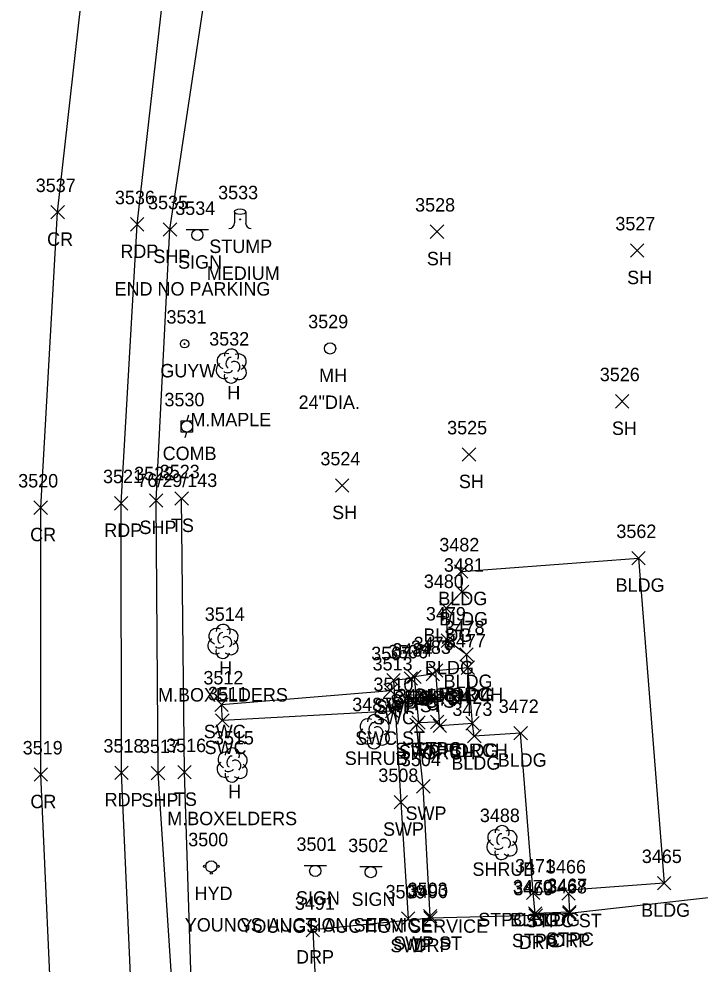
# Model space of a CAD drawing. Extents: x 1769141 to 1770911, y 735471 to 741449.
# Drawn here: x 1770463.6 to 1770565, y 737822.4 to 737963 of the extents above; entities that cross this region are included whole.
import ezdxf

# ---------------------------------------------------------------- set-up
doc = ezdxf.new("R2010")
doc.units = 0
for name, color, linetype in [('L_A', 7, 'Continuous'), ('L_C', 7, 'Continuous'), ('L_I', 7, 'Continuous'), ('L_TIC', 7, 'Continuous'), ('LBC', 7, 'Continuous'), ('LBF', 7, 'Continuous'), ('LELB', 7, 'Continuous'), ('LSH', 7, 'Continuous'), ('LTD', 7, 'Continuous'), ('LTS', 7, 'Continuous'), ('P_A', 7, 'Continuous'), ('P_I', 7, 'Continuous'), ('P_TIC', 7, 'Continuous'), ('PET', 7, 'Continuous'), ('PRC', 7, 'Continuous'), ('PSP', 7, 'Continuous'), ('R_A', 7, 'Continuous'), ('R_I', 7, 'Continuous'), ('R_TIC', 7, 'Continuous'), ('RDP', 7, 'Continuous'), ('RSW', 7, 'Continuous'), ('S_A', 7, 'Continuous'), ('S_C', 7, 'Continuous'), ('S_I', 7, 'Continuous'), ('SSGN', 7, 'Continuous'), ('U_A', 7, 'Continuous'), ('U_C', 7, 'Continuous'), ('U_I', 7, 'Continuous'), ('UP', 7, 'Continuous'), ('UPGW', 7, 'Continuous'), ('UUMH', 7, 'Continuous'), ('UWFH', 7, 'Continuous')]:
    doc.layers.add(name, color=color, linetype=linetype)

msp = doc.modelspace()

# ---------------------------------------------------------------- linework, layer by layer
at = {"layer": 'L_TIC'}
for points in [[(1770524.81, 737930.33), (1770526.81, 737932.33)], [(1770526.81, 737930.33), (1770524.81, 737932.33)], [(1770554.62, 737927.53), (1770556.62, 737929.53)], [(1770556.62, 737927.53), (1770554.62, 737929.53)], [(1770552.36, 737905.1), (1770554.36, 737907.1)], [(1770554.36, 737905.1), (1770552.36, 737907.1)], [(1770529.58, 737897.19), (1770531.58, 737899.19)], [(1770531.58, 737897.19), (1770529.58, 737899.19)], [(1770510.71, 737892.58), (1770512.71, 737894.58)], [(1770512.71, 737892.58), (1770510.71, 737894.58)], [(1770486.8, 737890.66), (1770488.8, 737892.66)], [(1770488.8, 737890.66), (1770486.8, 737892.66)], [(1770554.81, 737881.77), (1770556.81, 737883.77)], [(1770556.81, 737881.77), (1770554.81, 737883.77)], [(1770528.41, 737879.78), (1770530.41, 737881.78)], [(1770530.41, 737879.78), (1770528.41, 737881.78)], [(1770528.53, 737876.76), (1770530.53, 737878.76)], [(1770530.53, 737876.76), (1770528.53, 737878.76)], [(1770526.19, 737874.33), (1770528.19, 737876.33)], [(1770528.19, 737874.33), (1770526.19, 737876.33)], [(1770526.43, 737869.5), (1770528.43, 737871.5)], [(1770528.43, 737869.5), (1770526.43, 737871.5)], [(1770529.2, 737867.46), (1770531.2, 737869.46)], [(1770531.2, 737867.46), (1770529.2, 737869.46)], [(1770529.39, 737865.49), (1770531.39, 737867.49)], [(1770531.39, 737865.49), (1770529.39, 737867.49)], [(1770529.39, 737865.49), (1770531.39, 737867.49)], [(1770531.39, 737865.49), (1770529.39, 737867.49)], [(1770521.43, 737864.13), (1770523.43, 737866.13)], [(1770523.43, 737864.13), (1770521.43, 737866.13)], [(1770524.19, 737864.53), (1770526.19, 737866.53)], [(1770526.19, 737864.53), (1770524.19, 737866.53)], [(1770524.66, 737865.08), (1770526.66, 737867.08)], [(1770526.66, 737865.08), (1770524.66, 737867.08)], [(1770522.07, 737857.32), (1770524.07, 737859.32)], [(1770524.07, 737857.32), (1770522.07, 737859.32)], [(1770524.82, 737857.41), (1770526.82, 737859.41)], [(1770526.82, 737857.41), (1770524.82, 737859.41)], [(1770525.24, 737856.84), (1770527.24, 737858.84)], [(1770527.24, 737856.84), (1770525.24, 737858.84)], [(1770530.08, 737857.2), (1770532.08, 737859.2)], [(1770532.08, 737857.2), (1770530.08, 737859.2)], [(1770530.08, 737857.2), (1770532.08, 737859.2)], [(1770532.08, 737857.2), (1770530.08, 737859.2)], [(1770537.26, 737855.75), (1770539.26, 737857.75)], [(1770539.26, 737855.75), (1770537.26, 737857.75)], [(1770530.36, 737855.31), (1770532.36, 737857.31)], [(1770532.36, 737855.31), (1770530.36, 737857.31)], [(1770487.24, 737849.93), (1770489.24, 737851.93)], [(1770489.24, 737849.93), (1770487.24, 737851.93)], [(1770558.61, 737833.43), (1770560.61, 737835.43)], [(1770560.61, 737833.43), (1770558.61, 737835.43)], [(1770539.12, 737832.02), (1770541.12, 737834.02)], [(1770541.12, 737832.02), (1770539.12, 737834.02)], [(1770539.12, 737832.02), (1770541.12, 737834.02)], [(1770541.12, 737832.02), (1770539.12, 737834.02)], [(1770544.4, 737831.88), (1770546.4, 737833.88)], [(1770546.4, 737831.88), (1770544.4, 737833.88)], [(1770539.44, 737828.91), (1770541.44, 737830.91)], [(1770541.44, 737828.91), (1770539.44, 737830.91)], [(1770544.53, 737829.11), (1770546.53, 737831.11)], [(1770546.53, 737829.11), (1770544.53, 737831.11)]]:
    msp.add_lwpolyline(points, dxfattribs=at)
at = {"layer": 'LBC'}
for points in [[(1770559.61, 737834.43), (1770540.12, 737833.02), (1770538.26, 737856.75), (1770531.36, 737856.31), (1770531.08, 737858.2), (1770530.39, 737866.49), (1770530.2, 737868.46), (1770527.43, 737870.5), (1770527.19, 737875.33), (1770529.53, 737877.76), (1770529.41, 737880.78), (1770555.81, 737882.77)], [(1770555.81, 737882.77), (1770559.61, 737834.43)]]:
    msp.add_lwpolyline(points, dxfattribs=at)
at = {"layer": 'LBF'}
for points in [[(1770531.08, 737858.2), (1770526.24, 737857.84), (1770525.66, 737866.08), (1770530.39, 737866.49)], [(1770525.19, 737865.53), (1770522.43, 737865.13), (1770523.07, 737858.32), (1770525.82, 737858.41)], [(1770545.4, 737832.88), (1770545.53, 737830.11), (1770540.44, 737829.91), (1770540.12, 737833.02)]]:
    msp.add_lwpolyline(points, dxfattribs=at)
at = {"layer": 'LELB'}
msp.add_lwpolyline([(1770492.86, 737807.44), (1770489.41, 737813.76), (1770488.24, 737850.93), (1770487.8, 737891.66)], dxfattribs=at)
at = {"layer": 'LSH'}
for p, q in [((1770516.45, 737857.02), (1770516.45, 737857.02)), ((1770516.45, 737857.02), (1770516.45, 737857.02)), ((1770535.45, 737840.52), (1770535.45, 737840.52)), ((1770535.45, 737840.52), (1770535.45, 737840.52))]:
    msp.add_line(p, q, dxfattribs=at)
for centre in [(1770516.5, 737858.46), (1770535.5, 737841.95)]:
    msp.add_arc(centre, 1.05, 335.5272, 180.9563, dxfattribs=at)
for centre, major_axis, ratio, start_param, end_param in [((1770515.66, 737857.69), (1.21, -0.51), 0.895232, 1.570796, 4.712389), ((1770517.49, 737857.61), (-1.14, -0.48), 0.949671, 1.570796, 4.712389), ((1770515.37, 737856.32), (0.58, -1.04), 0.959034, 3.141593, 6.283185), ((1770516.24, 737857.48), (-0.208, -0.792), 0.645439, 3.141593, 6.283185), ((1770516.95, 737856.86), (-0.5, 0.667), 0.989748, 3.141593, 6.283185), ((1770515.99, 737856.27), (-0.625, -0.083), 0.423636, 0, 3.141593), ((1770517.45, 737856.19), (-1.09, 0.79), 0.841452, 1.570796, 4.712389), ((1770516.45, 737855.52), (0.26, 1.06), 0.942809, 1.570796, 4.712389), ((1770534.66, 737841.19), (1.21, -0.51), 0.895232, 1.570796, 4.712389), ((1770536.5, 737841.1), (-1.14, -0.48), 0.949671, 1.570796, 4.712389), ((1770534.37, 737839.81), (0.58, -1.04), 0.959034, 3.141593, 6.283185), ((1770535.25, 737840.98), (-0.208, -0.792), 0.645439, 3.141593, 6.283185), ((1770535.95, 737840.35), (-0.5, 0.667), 0.989748, 3.141593, 6.283185), ((1770536.45, 737839.69), (-1.09, 0.79), 0.841452, 1.570796, 4.712389), ((1770535.45, 737839.02), (0.26, 1.06), 0.942809, 1.570796, 4.712389), ((1770535, 737839.77), (-0.625, -0.083), 0.423636, 0, 3.141593)]:
    msp.add_ellipse(centre, major_axis=major_axis, ratio=ratio, start_param=start_param, end_param=end_param, dxfattribs=at)
at = {"layer": 'LTD'}
for p, q in [((1770495.16, 737911.39), (1770495.16, 737911.39)), ((1770495.16, 737911.39), (1770495.16, 737911.39)), ((1770493.93, 737870.45), (1770493.93, 737870.45)), ((1770493.93, 737870.45), (1770493.93, 737870.45)), ((1770495.3, 737852.06), (1770495.3, 737852.06)), ((1770495.3, 737852.06), (1770495.3, 737852.06))]:
    msp.add_line(p, q, dxfattribs=at)
for centre in [(1770495.21, 737912.82), (1770493.98, 737871.88), (1770495.35, 737853.5)]:
    msp.add_arc(centre, 1.05, 335.5272, 180.9563, dxfattribs=at)
for centre, major_axis, ratio, start_param, end_param in [((1770494.37, 737912.06), (1.21, -0.51), 0.895232, 1.570796, 4.712389), ((1770494.95, 737911.85), (-0.208, -0.792), 0.645439, 3.141593, 6.283185), ((1770495.66, 737911.22), (-0.5, 0.667), 0.989748, 3.141593, 6.283185), ((1770496.2, 737911.97), (-1.14, -0.48), 0.949671, 1.570796, 4.712389), ((1770494.08, 737910.68), (0.58, -1.04), 0.959034, 3.141593, 6.283185), ((1770496.16, 737910.56), (-1.09, 0.79), 0.841452, 1.570796, 4.712389), ((1770495.16, 737909.89), (0.26, 1.06), 0.942809, 1.570796, 4.712389), ((1770494.71, 737910.64), (-0.625, -0.083), 0.423636, 0, 3.141593), ((1770493.14, 737871.12), (1.21, -0.51), 0.895232, 1.570796, 4.712389), ((1770493.72, 737870.91), (-0.208, -0.792), 0.645439, 3.141593, 6.283185), ((1770494.97, 737871.03), (-1.14, -0.48), 0.949671, 1.570796, 4.712389), ((1770492.85, 737869.74), (0.58, -1.04), 0.959034, 3.141593, 6.283185), ((1770494.43, 737870.28), (-0.5, 0.667), 0.989748, 3.141593, 6.283185), ((1770494.93, 737869.62), (-1.09, 0.79), 0.841452, 1.570796, 4.712389), ((1770493.93, 737868.95), (0.26, 1.06), 0.942809, 1.570796, 4.712389), ((1770493.47, 737869.7), (-0.625, -0.083), 0.423636, 0, 3.141593), ((1770494.51, 737852.73), (1.21, -0.51), 0.895232, 1.570796, 4.712389), ((1770495.09, 737852.52), (-0.208, -0.792), 0.645439, 3.141593, 6.283185), ((1770496.34, 737852.65), (-1.14, -0.48), 0.949671, 1.570796, 4.712389), ((1770494.22, 737851.36), (0.58, -1.04), 0.959034, 3.141593, 6.283185), ((1770495.8, 737851.9), (-0.5, 0.667), 0.989748, 3.141593, 6.283185), ((1770496.3, 737851.23), (-1.09, 0.79), 0.841452, 1.570796, 4.712389), ((1770495.3, 737850.56), (0.26, 1.06), 0.942809, 1.570796, 4.712389), ((1770494.84, 737851.31), (-0.625, -0.083), 0.423636, 0, 3.141593)]:
    msp.add_ellipse(centre, major_axis=major_axis, ratio=ratio, start_param=start_param, end_param=end_param, dxfattribs=at)
at = {"layer": 'LTS'}
for p, q in [((1770495.66, 737934.3), (1770495.66, 737932.63)), ((1770497.33, 737934.13), (1770497.33, 737934.3)), ((1770497.33, 737934.3), (1770497.33, 737932.63)), ((1770496.5, 737933.16), (1770496.5, 737933.16)), ((1770496.5, 737933.16), (1770496.5, 737933.16)), ((1770496.5, 737933.13), (1770496.5, 737933.13))]:
    msp.add_line(p, q, dxfattribs=at)
msp.add_circle((1770496.5, 737933.16), 0.0833, dxfattribs=at)
for centre, start, end in [((1770494.83, 737932.63), 270, 360), ((1770498.16, 737932.63), 180, 270)]:
    msp.add_arc(centre, 0.833, start, end, dxfattribs=at)
msp.add_ellipse((1770496.5, 737934.3), major_axis=(-0.833, 0), ratio=0.5, dxfattribs=at)
at = {"layer": 'P_TIC'}
for points in [[(1770468.34, 737933.23), (1770470.34, 737935.23)], [(1770470.34, 737933.23), (1770468.34, 737935.23)], [(1770480.19, 737931.42), (1770482.19, 737933.42)], [(1770482.19, 737931.42), (1770480.19, 737933.42)], [(1770485.06, 737930.67), (1770487.06, 737932.67)], [(1770487.06, 737930.67), (1770485.06, 737932.67)], [(1770465.82, 737889.29), (1770467.82, 737891.29)], [(1770467.82, 737889.29), (1770465.82, 737891.29)], [(1770477.8, 737889.93), (1770479.8, 737891.93)], [(1770479.8, 737889.93), (1770477.8, 737891.93)], [(1770482.99, 737890.36), (1770484.99, 737892.36)], [(1770484.99, 737890.36), (1770482.99, 737892.36)], [(1770477.86, 737849.86), (1770479.86, 737851.86)], [(1770479.86, 737849.86), (1770477.86, 737851.86)], [(1770483.28, 737849.79), (1770485.28, 737851.79)], [(1770485.28, 737849.79), (1770483.28, 737851.79)], [(1770465.84, 737849.58), (1770467.84, 737851.58)], [(1770467.84, 737849.58), (1770465.84, 737851.58)]]:
    msp.add_lwpolyline(points, dxfattribs=at)
at = {"layer": 'PET'}
msp.add_lwpolyline([(1770480.71, 737808.5), (1770478.86, 737850.86), (1770478.8, 737890.93), (1770481.19, 737932.42), (1770486.18, 737976.53), (1770491.62, 738013.47), (1770502.41, 738078.7), (1770511.1, 738132.78), (1770519.35, 738183.15), (1770528.05, 738233.56)], dxfattribs=at)
at = {"layer": 'PRC'}
msp.add_lwpolyline([(1770468.76, 737807.58), (1770466.84, 737850.58), (1770466.82, 737890.29), (1770469.34, 737934.23), (1770474.31, 737978.71), (1770479.69, 738015.04), (1770490.28, 738081.51), (1770499.05, 738134.54), (1770507.77, 738186.68), (1770516.39, 738236.25)], dxfattribs=at)
at = {"layer": 'PSP'}
msp.add_lwpolyline([(1770486.55, 737816.81), (1770484.28, 737850.79), (1770483.99, 737891.36), (1770486.06, 737931.67), (1770492.57, 737975.17), (1770497.3, 738012.43), (1770501.89, 738042.39), (1770501.76, 738044.7), (1770499.5, 738044.97), (1770500.56, 738049.22), (1770502.3, 738050.11), (1770506.67, 738077.79), (1770511.72, 738105.49), (1770515.85, 738132.28), (1770518.33, 738152.88), (1770523.83, 738182.57), (1770531.42, 738212.51), (1770539.31, 738265.32)], dxfattribs=at)
at = {"layer": 'R_TIC'}
for points in [[(1770520.93, 737863.87), (1770522.93, 737865.87)], [(1770522.93, 737863.87), (1770520.93, 737865.87)], [(1770518.35, 737863.6), (1770520.35, 737865.6)], [(1770520.35, 737863.6), (1770518.35, 737865.6)], [(1770517.92, 737862.07), (1770519.92, 737864.07)], [(1770519.92, 737862.07), (1770517.92, 737864.07)], [(1770492.73, 737859.99), (1770494.73, 737861.99)], [(1770494.73, 737859.99), (1770492.73, 737861.99)], [(1770518.13, 737859.01), (1770520.13, 737861.01)], [(1770520.13, 737859.01), (1770518.13, 737861.01)], [(1770492.86, 737857.63), (1770494.86, 737859.63)], [(1770494.86, 737857.63), (1770492.86, 737859.63)], [(1770521.78, 737857), (1770523.78, 737859)], [(1770523.78, 737857), (1770521.78, 737859)], [(1770522.77, 737847.84), (1770524.77, 737849.84)], [(1770524.77, 737847.84), (1770522.77, 737849.84)], [(1770519.42, 737845.48), (1770521.42, 737847.48)], [(1770521.42, 737845.48), (1770519.42, 737847.48)], [(1770539.49, 737828.63), (1770541.49, 737830.63)], [(1770541.49, 737828.63), (1770539.49, 737830.63)], [(1770544.48, 737828.91), (1770546.48, 737830.91)], [(1770546.48, 737828.91), (1770544.48, 737830.91)], [(1770520.51, 737828.16), (1770522.51, 737830.16)], [(1770522.51, 737828.16), (1770520.51, 737830.16)], [(1770523.78, 737828.51), (1770525.78, 737830.51)], [(1770525.78, 737828.51), (1770523.78, 737830.51)], [(1770523.84, 737828.21), (1770525.84, 737830.21)], [(1770525.84, 737828.21), (1770523.84, 737830.21)], [(1770506.34, 737826.47), (1770508.34, 737828.47)], [(1770508.34, 737826.47), (1770506.34, 737828.47)]]:
    msp.add_lwpolyline(points, dxfattribs=at)
at = {"layer": 'RDP'}
msp.add_lwpolyline([(1770490.29, 737787.37), (1770507.99, 737789.23), (1770543.91, 737792.74), (1770589.63, 737792.76), (1770587.83, 737818.09), (1770572.93, 737817.31), (1770571.5, 737832.84), (1770545.48, 737829.91), (1770540.49, 737829.63), (1770524.84, 737829.21), (1770507.34, 737827.47), (1770508.38, 737805.41), (1770496.94, 737803.45), (1770492.73, 737804.13), (1770488.37, 737807.82)], dxfattribs=at)
at = {"layer": 'RSW'}
for points in [[(1770521.93, 737864.87), (1770519.35, 737864.6), (1770520.42, 737846.48), (1770521.51, 737829.16)], [(1770519.13, 737860.01), (1770493.86, 737858.63), (1770493.73, 737860.99), (1770518.92, 737863.07)], [(1770524.78, 737829.51), (1770523.77, 737848.84), (1770522.78, 737858)]]:
    msp.add_lwpolyline(points, dxfattribs=at)
at = {"layer": 'SSGN'}
for p, q in [((1770488.48, 737931.68), (1770491.82, 737931.68)), ((1770490.13, 737930.85), (1770490.13, 737930.85)), ((1770506.03, 737837.08), (1770509.36, 737837.08)), ((1770507.68, 737836.25), (1770507.68, 737836.25)), ((1770514.31, 737836.91), (1770517.64, 737836.91)), ((1770515.95, 737836.07), (1770515.95, 737836.07))]:
    msp.add_line(p, q, dxfattribs=at)
for centre in [(1770490.13, 737930.85), (1770507.68, 737836.25), (1770515.95, 737836.07)]:
    msp.add_circle(centre, 0.833, dxfattribs=at)
at = {"layer": 'UP'}
for p, q in [((1770488.83, 737904.03), (1770488.58, 737903.2)), ((1770487.75, 737901.53), (1770487.75, 737903.2)), ((1770487.75, 737903.2), (1770489.42, 737903.2)), ((1770488.58, 737902.36), (1770488.58, 737902.36)), ((1770489.42, 737903.2), (1770489.42, 737901.53)), ((1770489.42, 737901.53), (1770487.75, 737901.53)), ((1770488.33, 737900.7), (1770488.58, 737901.53))]:
    msp.add_line(p, q, dxfattribs=at)
msp.add_circle((1770488.58, 737902.36), 0.833, dxfattribs=at)
at = {"layer": 'UPGW'}
for radius in [0.625, 0.0833]:
    msp.add_circle((1770488.23, 737914.66), radius, dxfattribs=at)
at = {"layer": 'UUMH'}
for p, q in [((1770509.9, 737913.97), (1770509.9, 737913.97)), ((1770510.74, 737913.97), (1770510.74, 737913.97))]:
    msp.add_line(p, q, dxfattribs=at)
msp.add_circle((1770509.9, 737913.97), 0.833, dxfattribs=at)
at = {"layer": 'UWFH'}
msp.add_line((1770492.21, 737836.92), (1770492.21, 737836.92), dxfattribs=at)
for centre, radius in [((1770492.21, 737836.92), 0.833), ((1770491.21, 737836.92), 0.167), ((1770493.21, 737836.92), 0.167), ((1770492.21, 737835.92), 0.167)]:
    msp.add_circle(centre, radius, dxfattribs=at)

# ---------------------------------------------------------------- texts
at = {"layer": 'L_A'}
for s, p in [('STUMP', (1770491.92, 737928.16)), ('SH', (1770524.3, 737926.33)), ('SH', (1770554.11, 737923.53)), ('H', (1770494.6, 737906.39)), ('SH', (1770551.85, 737901.1)), ('SH', (1770529.07, 737893.19)), ('SH', (1770510.2, 737888.58)), ('TS', (1770486.21, 737886.66)), ('BLDG', (1770552.4, 737877.77)), ('BLDG', (1770526.01, 737875.78)), ('BLDG', (1770526.12, 737872.76)), ('BLDG', (1770523.78, 737870.33)), ('H', (1770493.37, 737865.45)), ('BLDG', (1770524.02, 737865.5)), ('BLDG', (1770526.79, 737863.46)), ('PORCH', (1770521.28, 737861.08)), ('PORCH', (1770526.01, 737861.49)), ('BLDG', (1770526.98, 737861.49)), ('STPC ST', (1770518.83, 737860.53)), ('STPC', (1770518.94, 737860.13)), ('STPC', (1770519.59, 737853.32)), ('PORCH', (1770521.86, 737852.84)), ('STPC', (1770522.33, 737853.41)), ('PORCH', (1770526.7, 737853.2)), ('BLDG', (1770527.67, 737853.2)), ('SHRUB', (1770512.08, 737852.02)), ('BLDG', (1770527.95, 737851.31)), ('BLDG', (1770534.85, 737851.75)), ('H', (1770494.73, 737847.06)), ('TS', (1770486.65, 737845.93)), ('SHRUB', (1770531.08, 737835.52)), ('BLDG', (1770556.2, 737829.43)), ('STPC BLDG', (1770531.95, 737828.02)), ('BLDG', (1770536.71, 737828.02)), ('STPC ST', (1770539.04, 737827.88)), ('STPC', (1770536.96, 737824.91)), ('STPC', (1770542.04, 737825.11))]:
    msp.add_text(s, height=2, dxfattribs=at).set_placement(p)
at = {"layer": 'L_C'}
for s, p in [('MEDIUM', (1770491.55, 737924.16)), ('M.MAPLE', (1770489.1, 737902.39)), ('M.BOXELDERS', (1770484.29, 737861.45)), ('M.BOXELDERS', (1770485.66, 737843.06))]:
    msp.add_text(s, height=2, dxfattribs=at).set_placement(p)
at = {"layer": 'L_I'}
for s, p in [('3533', (1770493.23, 737936.16)), ('3528', (1770522.55, 737934.33)), ('3527', (1770552.36, 737931.53)), ('3532', (1770491.9, 737914.39)), ('3526', (1770550.04, 737909.1)), ('3525', (1770527.32, 737901.19)), ('3524', (1770508.45, 737896.58)), ('3523', (1770484.54, 737894.66)), ('3562', (1770552.51, 737885.77)), ('3482', (1770526.16, 737883.78)), ('3481', (1770526.83, 737880.76)), ('3480', (1770523.85, 737878.33)), ('3514', (1770491.24, 737873.45)), ('3479', (1770524.16, 737873.5)), ('3478', (1770526.94, 737871.46)), ('3477', (1770527.13, 737869.49)), ('3477', (1770527.13, 737869.49)), ('3484', (1770519.17, 737868.13)), ('3483', (1770521.93, 737868.53)), ('3476', (1770522.34, 737869.08)), ('3485', (1770519.81, 737861.32)), ('3486', (1770522.51, 737861.41)), ('3474', (1770527.82, 737861.2)), ('3474', (1770527.82, 737861.2)), ('3487', (1770513.19, 737860.02)), ('3475', (1770522.98, 737860.84)), ('3472', (1770535, 737859.75)), ('3473', (1770528.1, 737859.31)), ('3516', (1770485.49, 737853.93)), ('3515', (1770492.61, 737855.06)), ('3488', (1770532.19, 737843.52)), ('3465', (1770556.3, 737837.43)), ('3471', (1770537.42, 737836.02)), ('3471', (1770537.42, 737836.02)), ('3466', (1770542.03, 737835.88)), ('3470', (1770537.1, 737832.91)), ('3467', (1770542.22, 737833.11))]:
    msp.add_text(s, height=2, dxfattribs=at).set_placement(p)
at = {"layer": 'P_A'}
for s, p in [('CR', (1770467.77, 737929.23)), ('RDP', (1770478.68, 737927.42)), ('SHP', (1770483.59, 737926.67)), ('SHP', (1770481.52, 737886.36)), ('CR', (1770465.25, 737885.29)), ('RDP', (1770476.28, 737885.93)), ('CR', (1770465.28, 737845.58)), ('RDP', (1770476.34, 737845.86)), ('SHP', (1770481.81, 737845.79))]:
    msp.add_text(s, height=2, dxfattribs=at).set_placement(p)
at = {"layer": 'P_I'}
for s, p in [('3537', (1770466.08, 737937.23)), ('3536', (1770477.87, 737935.42)), ('3535', (1770482.8, 737934.67)), ('3520', (1770463.47, 737893.29)), ('3521', (1770476.1, 737893.93)), ('3522', (1770480.73, 737894.36)), ('3519', (1770464.14, 737853.58)), ('3518', (1770476.16, 737853.86)), ('3517', (1770481.59, 737853.79))]:
    msp.add_text(s, height=2, dxfattribs=at).set_placement(p)
at = {"layer": 'R_A'}
for s, p in [('SWP ST', (1770516.42, 737859.87)), ('SWP', (1770516.72, 737859.6)), ('SWC', (1770516.28, 737858.07)), ('SWC', (1770491.09, 737855.99)), ('SWC ST', (1770513.63, 737855.01)), ('SWC', (1770491.22, 737853.63)), ('SWP', (1770520.14, 737853)), ('SWP', (1770521.13, 737843.84)), ('SWP', (1770517.78, 737841.48)), ('SWP ST', (1770519.28, 737824.51)), ('DRP', (1770537.98, 737824.63)), ('DRP', (1770542.97, 737824.91)), ('SWP', (1770518.87, 737824.16)), ('DRP', (1770522.33, 737824.21)), ('DRP', (1770504.83, 737822.47))]:
    msp.add_text(s, height=2, dxfattribs=at).set_placement(p)
at = {"layer": 'R_I'}
for s, p in [('3507', (1770516.02, 737867.6)), ('3506', (1770518.53, 737867.87)), ('3513', (1770516.23, 737866.07)), ('3512', (1770491.04, 737863.99)), ('3510', (1770516.35, 737863.01)), ('3511', (1770491.73, 737861.63)), ('3505', (1770519.44, 737861)), ('3504', (1770520.43, 737851.84)), ('3508', (1770517.08, 737849.48)), ('3468', (1770542.18, 737832.91)), ('3509', (1770518.16, 737832.16)), ('3503', (1770521.44, 737832.51)), ('3490', (1770521.49, 737832.21)), ('3469', (1770537.18, 737832.63)), ('3491', (1770504.65, 737830.47))]:
    msp.add_text(s, height=2, dxfattribs=at).set_placement(p)
at = {"layer": 'S_A'}
for p in [(1770487.27, 737925.83), (1770504.82, 737831.23), (1770513.09, 737831.05)]:
    msp.add_text('SIGN', height=2, dxfattribs=at).set_placement(p)
at = {"layer": 'S_C'}
for s, p in [('END NO PARKING', (1770477.82, 737921.83)), ('YOUNGS AUCTION SERVICE', (1770488.27, 737827.23)), ('YOUNGS AUCTION SERVICE', (1770496.55, 737827.05))]:
    msp.add_text(s, height=2, dxfattribs=at).set_placement(p)
at = {"layer": 'S_I'}
for s, p in [('3534', (1770486.85, 737933.83)), ('3501', (1770504.89, 737839.23)), ('3502', (1770512.59, 737839.05))]:
    msp.add_text(s, height=2, dxfattribs=at).set_placement(p)
at = {"layer": 'U_A'}
for s, p in [('GUYW', (1770484.63, 737909.66)), ('MH', (1770508.27, 737908.97)), ('COMB', (1770484.97, 737897.36)), ('HYD', (1770489.73, 737831.92))]:
    msp.add_text(s, height=2, dxfattribs=at).set_placement(p)
at = {"layer": 'U_C'}
for s, p in [('24"DIA.', (1770505.21, 737904.97)), ('76/29/143', (1770481.2, 737893.36))]:
    msp.add_text(s, height=2, dxfattribs=at).set_placement(p)
at = {"layer": 'U_I'}
for s, p in [('3531', (1770485.54, 737917.66)), ('3529', (1770506.64, 737916.97)), ('3530', (1770485.24, 737905.36)), ('3500', (1770488.78, 737839.92))]:
    msp.add_text(s, height=2, dxfattribs=at).set_placement(p)

doc.saveas('drawing.dxf')
